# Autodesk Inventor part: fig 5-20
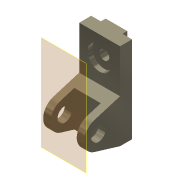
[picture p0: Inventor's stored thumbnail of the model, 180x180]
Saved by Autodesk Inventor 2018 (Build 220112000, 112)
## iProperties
Shininess: 65.0
Angle Display Precision: 2
Document Length Units: 11269
Document Angle Units: 11279
Document Time Units: 11290
Document Mass Units: 11283
Document Length Units Precision: 3
Document Angle Units Precision: 2
Compacted: False
Created: 2001-11
Part Number: fig 5-20
Document SubType Name: Modeling
Designer: Renu Muthoo
Density: 1 g/cm^3
Material: Generic
Appearance: Metal-Titanium (Polished)
Density: 0.0
Volumn: 0.0
Area: 0.0
PropertySet Name: Model Information
Control State: 0
Master: False
Checked Out: False
Author: Renu Muthoo
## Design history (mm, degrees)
node "Sketch1"
sketch "Sketch2"
  geometry: L1 (33.257, 104.664)-(33.257, -75.336); L2 (33.257, -75.336)-(8.257, -75.336); L3 (8.257, -75.336)-(-45.451, -59.045); L4 (-45.451, -1.628)-(8.257, 14.664); L5 (8.257, 14.664)-(8.257, 104.664); L6 (8.257, 104.664)-(33.257, 104.664); C1 r 15 at (-36.743, -30.336); A1 r 30 centre (-36.743, -30.336) between (-45.451, -1.628) and (-45.451, -59.045)
  constraints: 12 end point, 2 centre point, 2 equal length, 2 parallel, 2 point on circle, 2 tangent, 1 coincident, 1 perpendicular, 1 vertical
  dimensions: "d0" = 180 distance of L1.start L1.end; "d1" = 30 radius of A1; "d2" = 25 distance of L5.end L1.start; "d3" = 45 distance from line of L2 A1.centre; "d4" = 70 distance from line of L1 A1.centre; "d5" = 30 diameter of C1
extrude "Extrusion1" new body sketch "Sketch2" distance "d6" = 85; taper "d7" = 0 deg
workplane "Work Plane1"
sketch "Sketch3"
  geometry: L1 (15, 62.364)-(70, 62.364); L2 (70, 62.364)-(70, -52.386); L3 (70, -52.386)-(15, -52.386); L4 (15, -52.386)-(15, 62.364); L5 (0, -45)-(0, -28.708) reference
  constraints: 8 end point, 2 parallel, 1 horizontal, 1 perpendicular
  dimensions: "d8" = 55 distance of L1.start L1.end; "d9" = 15 distance between parallel lines of L5 L4
extrude "Extrusion2" cut sketch "Sketch3" distance "d10" = 50; taper "d11" = 0 deg
sketch "Sketch4"
  geometry: L1 (0, 25)-(85, 25) reference; L2 (0, 0)-(0, 25) reference; L3 (20, 25)-(65, 25); L4 (65, 25)-(65, 35); L5 (65, 35)-(20, 35); L6 (20, 35)-(20, 25)
  constraints: 8 end point, 2 parallel, 1 horizontal, 1 perpendicular, 1 point on line
  dimensions: "d12" = 45 distance of L4.end L5.end; "d13" = 10 distance of L3.end L4.end; "d14" = 20 distance between parallel lines of L2 L6
extrude "Extrusion3" join sketch "Sketch4" stored distance "d15" = 50; taper "d16" = 0 deg
sketch "Sketch5"
  geometry: L1 (85, 0)-(85, 90) reference; L2 (0, 90)-(85, 90) reference; 1 further point
  dimensions: "d17" = 42 distance from line of L2 point (42.5, 48); "d18" = 42.5 distance from line of L1 point (42.5, 48)
hole "Hole1" sketch "Sketch5" at (42.5, 48) diameter "d19" = 20; stored, may be unused: countersink angle "d23" = 82 deg, drill point angle "d25" = 118 deg; dims "d20" = 6, "d21" = 50, "d22" = 10, "d24" = 8
workplane "Work Plane10"
body "Solid1"
